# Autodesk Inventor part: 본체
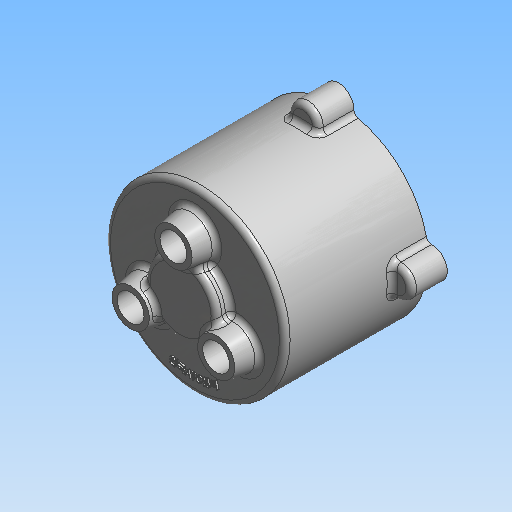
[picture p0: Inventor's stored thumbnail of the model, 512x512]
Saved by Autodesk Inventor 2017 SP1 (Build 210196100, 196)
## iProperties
Created: 2021-07
Part Number: 본체
Document SubType Name: 모델링
Designer: mdu
Material: 알루미늄 6061
Density: 1 g/cm^3
Appearance: 알루미늄 - 평지
변환 표준: STEP AP214IS
파일 이름: C:\Users\SeoGD\Desktop\?쒗뿕\紐몄껜.stp
전처리기: Build: 253, Release: 2010 SP1 - Date: Wed 07/29/2009
전송 단위: 밀리미터
불확실성: 0.01
Author: mdu
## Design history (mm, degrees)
sketch "스케치2"
  geometry: C1 r 50 at (0, 0); 1 further point
  constraints: 1 centre point, 1 coincident
  dimensions: "d9" = 100 diameter of C1
extrude "돌출2" new body sketch "스케치2" distance "d10" = 80; taper "d11" = 0 deg
feature "쉘1" dims "d12" = 5
sketch "스케치3" dims "d13" = 55
  geometry: C1 r 7.5 at (0, 27.5); C2 r 12.5 at (0, 27.5); 2 further points
  constraints: 2 centre point, 2 coincident, 2 vertical alignment, 2 other
  dimensions: "d14" = 15 diameter of C1; "d15" = 25 diameter of C2
extrude "돌출3" join sketch "스케치3" distance "d16" = 12; taper "d17" = -10 deg
sketch "스케치4"
  geometry: L1 (0, 0)-(0, 88); L2 (0, 70)-(14, 70); L3 (-45, 75)-(45, 75) reference; L4 (-50, 80)-(50, 80) reference; L5 (14, 70)-(14, 75); L6 (20, 80)-(20, 88); L7 (20, 88)-(0, 88); L8 (20, 80)-(14, 75)
  constraints: 12 end point, 3 point on line, 2 perpendicular, 1 vertical
  dimensions: "d34" = 40 diameter of L6 L1; "d35" = 90 deg angle of L5 L3; "d36" = 5 distance between parallel lines of L2 L3; "d37" = 8 distance between parallel lines of L7 L4; "d51" = 28 diameter of L5.end L1
revolve "회전1" sketch "스케치4" stored, may be unused: angle "d38" = 90 deg
hole "구멍3" diameter "d41" = 15; stored, may be unused: countersink angle "d45" = 90 deg, drill point angle "d47" = 0 deg; dims "d39" = 10, "d40" = 10, "d42" = 6, "d43" = 22, "d44" = 13, "d46" = 15
chamfer "모따기2" distance "d48" = 1; stored, may be unused: second distance "d49" = 2, angle "d50" = 45 deg
fillet "모깎기4" dims "d78" = 3
hole "구멍2" diameter "d20" = 15; stored, may be unused: countersink angle "d24" = 90 deg, drill point angle "d26" = 118 deg; dims "d21" = 6, "d22" = 25, "d23" = 1, "d25" = 15, "d76" = 10, "d77" = 10
chamfer "모따기1" distance "d27" = 1; stored, may be unused: second distance "d28" = 2, angle "d29" = 45 deg
sketch "스케치9"
  geometry: C1 r 12.5 at (0, 0) reference; C2 r 12.5 at (-23.816, -41.25) reference; C3 r 12.5 at (23.816, -41.25) reference; 1 further point
extrude "돌출5" cut sketch "스케치9" stored distance "d79" = 10; taper "d80" = 0 deg
fillet "모깎기1" dims "d52" = 3
fillet "모깎기2" dims "d53" = 3, "d72" = 0.2
sketch "스케치5"
  geometry: A1 r 50 centre (0, 0) between (50, 0) and (-8.074, 49.344) reference; A2 r 8.5 centre (0, 52) between (8.074, 49.344) and (-8.074, 49.344); 1 further point
  constraints: 5 point on circle, 1 centre point, 1 horizontal alignment
  dimensions: "d54" = 90 deg dimension on point (0, 0) A2.centre A1.start; "d55" = 52 distance of A2.centre point (0, 0); "d56" = 17 diameter of A2
extrude "돌출4" join sketch "스케치5" distance "d57" = 20; taper "d58" = 0 deg
fillet "모깎기3" dims "d59" = 3
hole "구멍4" diameter "d62" = 4.134; stored, may be unused: countersink angle "d66" = 90 deg, drill point angle "d68" = 118 deg; dims "d60" = 10, "d61" = 10, "d63" = 12, "d64" = 22, "d65" = 13, "d67" = 15
sketch "스케치6"
  geometry: C1 r 47 at (0, 0) reference; C2 r 42.5 at (0, 0); 1 further point
  constraints: 1 centre point, 1 coincident, 1 other
  dimensions: "d73" = 85 diameter of C2
feature "엠보싱1" sketch "스케치6" dims "d34" = 40, "d35" = 90 deg, "d36" = 5, "d37" = 8, "d51" = 28, "d74" = 1, "d75" = 0
node "솔리드1"
node "솔리드 본체"
node "곡면 본체"
pattern_circular "원형 패턴1" dims angle "d31" = 360 deg
pattern_circular "원형 패턴2" dims angle "d70" = 360 deg
node "솔리드2"
